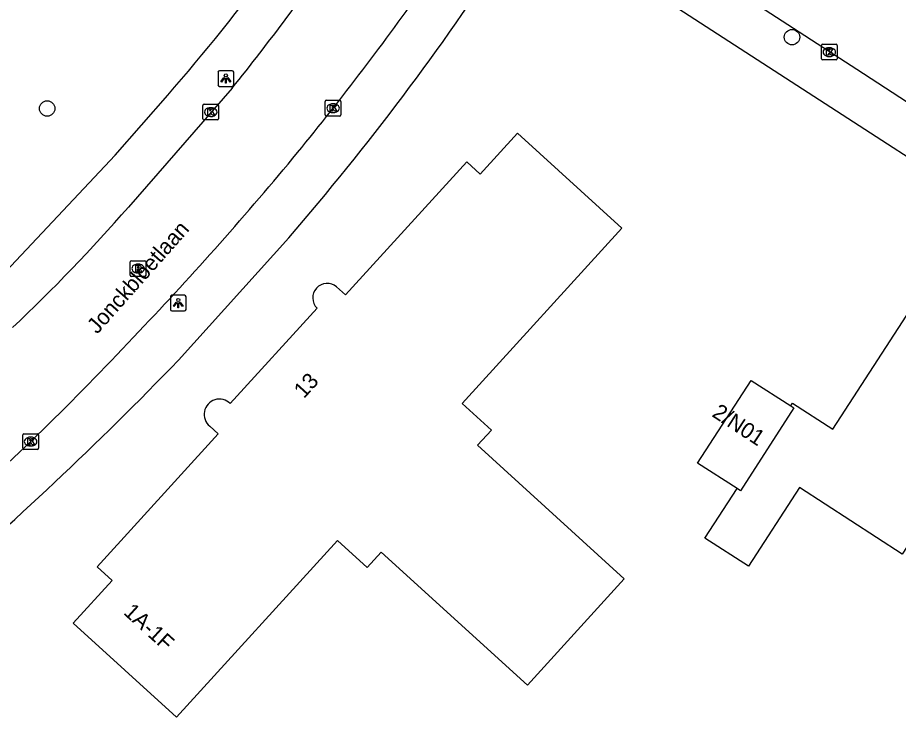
# Model space of a CAD drawing. Extents: x 161141 to 161601, y 381708 to 382245.
# Drawn here: x 161326.4 to 161382.4, y 382081.9 to 382126.6 of the extents above; entities that cross this region are included whole.
import ezdxf

# ---------------------------------------------------------------- set-up
doc = ezdxf.new("R2010")
doc.units = 0
for name, color, linetype in [('IMGEO_Boom', 7, 'Continuous'), ('IMGEO_Kolk', 7, 'Continuous'), ('IMGEO_Lichtpunt', 7, 'Continuous'), ('IMGEO_Openbare_ruimte_label', 7, 'Continuous'), ('IMGEO_Pand', 7, 'Continuous'), ('IMGEO_Pand_nummerreeks', 7, 'Continuous'), ('IMGEO_Rijbaan_lokaal_open', 7, 'Continuous'), ('IMGEO_Rioolput', 7, 'Continuous'), ('IMGEO_Voetpad_open', 7, 'Continuous')]:
    doc.layers.add(name, color=color, linetype=linetype)

msp = doc.modelspace()

# ---------------------------------------------------------------- linework, layer by layer
at = {"layer": 'IMGEO_Boom'}
for centre in [(161375.634, 382125.332), (161328.284, 382120.794)]:
    msp.add_circle(centre, 0.489, dxfattribs=at)
at = {"layer": 'IMGEO_Kolk'}
for p, q in [((161377.504, 382123.953), (161377.504, 382124.805)), ((161377.579, 382124.879), (161378.431, 382124.879)), ((161377.992, 382124.659), (161378.017, 382124.659)), ((161378.505, 382124.805), (161378.505, 382123.953)), ((161378.431, 382123.879), (161377.579, 382123.879)), ((161378.015, 382124.099), (161377.99, 382124.099)), ((161338.258, 382121.065), (161339.11, 382121.065)), ((161345.96, 382120.389), (161345.96, 382121.241)), ((161346.035, 382121.315), (161346.887, 382121.315)), ((161346.448, 382121.095), (161346.473, 382121.095)), ((161346.961, 382121.241), (161346.961, 382120.389)), ((161338.183, 382120.139), (161338.183, 382120.991)), ((161338.671, 382120.845), (161338.696, 382120.845)), ((161339.184, 382120.991), (161339.184, 382120.139)), ((161346.471, 382120.535), (161346.446, 382120.535)), ((161339.11, 382120.065), (161338.258, 382120.065)), ((161338.694, 382120.285), (161338.669, 382120.285)), ((161346.887, 382120.315), (161346.035, 382120.315)), ((161326.728, 382099.183), (161326.728, 382100.035)), ((161326.803, 382100.109), (161327.655, 382100.109)), ((161327.216, 382099.889), (161327.241, 382099.889)), ((161327.729, 382100.035), (161327.729, 382099.183)), ((161327.239, 382099.329), (161327.214, 382099.329)), ((161327.655, 382099.109), (161326.803, 382099.109))]:
    msp.add_line(p, q, dxfattribs=at)
for points in [[(161377.504, 382123.953), (161377.504, 382124.805)], [(161377.579, 382124.879), (161378.431, 382124.879)], [(161377.825, 382124.579), (161377.948, 382124.579), (161377.948, 382124.428), (161378.078, 382124.579), (161378.242, 382124.579), (161378.096, 382124.428), (161378.249, 382124.179), (161378.097, 382124.179), (161378.012, 382124.343), (161377.948, 382124.276), (161377.948, 382124.179), (161377.825, 382124.179), (161377.825, 382124.579)], [(161378.505, 382124.805), (161378.505, 382123.953)], [(161378.431, 382123.879), (161377.579, 382123.879)], [(161338.258, 382121.065), (161339.11, 382121.065)], [(161345.96, 382120.389), (161345.96, 382121.241)], [(161346.035, 382121.315), (161346.887, 382121.315)], [(161346.281, 382121.015), (161346.404, 382121.015), (161346.404, 382120.864), (161346.534, 382121.015), (161346.698, 382121.015), (161346.552, 382120.864), (161346.705, 382120.615), (161346.553, 382120.615), (161346.468, 382120.779), (161346.404, 382120.712), (161346.404, 382120.615), (161346.281, 382120.615), (161346.281, 382121.015)], [(161346.961, 382121.241), (161346.961, 382120.389)], [(161338.183, 382120.139), (161338.183, 382120.991)], [(161338.504, 382120.765), (161338.627, 382120.765), (161338.627, 382120.614), (161338.757, 382120.765), (161338.921, 382120.765), (161338.775, 382120.614), (161338.928, 382120.365), (161338.776, 382120.365), (161338.691, 382120.529), (161338.627, 382120.462), (161338.627, 382120.365), (161338.504, 382120.365), (161338.504, 382120.765)], [(161339.184, 382120.991), (161339.184, 382120.139)], [(161339.11, 382120.065), (161338.258, 382120.065)], [(161346.887, 382120.315), (161346.035, 382120.315)], [(161326.728, 382099.183), (161326.728, 382100.035)], [(161326.803, 382100.109), (161327.655, 382100.109)], [(161327.049, 382099.809), (161327.172, 382099.809), (161327.172, 382099.658), (161327.302, 382099.809), (161327.466, 382099.809), (161327.32, 382099.658), (161327.473, 382099.409), (161327.321, 382099.409), (161327.236, 382099.573), (161327.172, 382099.506), (161327.172, 382099.409), (161327.049, 382099.409), (161327.049, 382099.809)], [(161327.729, 382100.035), (161327.729, 382099.183)], [(161327.655, 382099.109), (161326.803, 382099.109)]]:
    msp.add_lwpolyline(points, dxfattribs=at)
for centre, start, end in [((161377.581, 382124.803), 91.552, 178.448), ((161377.581, 382124.803), 91.552, 178.448), ((161378.429, 382124.803), 1.552, 88.448), ((161378.429, 382124.803), 1.552, 88.448), ((161377.581, 382123.955), 181.552, 268.448), ((161377.581, 382123.955), 181.552, 268.448), ((161378.429, 382123.955), 271.552, 358.448), ((161378.429, 382123.955), 271.552, 358.448), ((161338.26, 382120.989), 91.552, 178.448), ((161338.26, 382120.989), 91.552, 178.448), ((161339.108, 382120.989), 1.552, 88.448), ((161339.108, 382120.989), 1.552, 88.448), ((161346.037, 382121.239), 91.552, 178.448), ((161346.037, 382121.239), 91.552, 178.448), ((161346.885, 382121.239), 1.552, 88.448), ((161346.885, 382121.239), 1.552, 88.448), ((161338.26, 382120.141), 181.552, 268.448), ((161338.26, 382120.141), 181.552, 268.448), ((161339.108, 382120.141), 271.552, 358.448), ((161339.108, 382120.141), 271.552, 358.448), ((161346.037, 382120.391), 181.552, 268.448), ((161346.037, 382120.391), 181.552, 268.448), ((161346.885, 382120.391), 271.552, 358.448), ((161346.885, 382120.391), 271.552, 358.448), ((161326.805, 382100.033), 91.552, 178.448), ((161326.805, 382100.033), 91.552, 178.448), ((161327.653, 382100.033), 1.552, 88.448), ((161327.653, 382100.033), 1.552, 88.448), ((161326.805, 382099.185), 181.552, 268.448), ((161326.805, 382099.185), 181.552, 268.448), ((161327.653, 382099.185), 271.552, 358.448), ((161327.653, 382099.185), 271.552, 358.448)]:
    msp.add_arc(centre, 0.0765, start, end, dxfattribs=at)
for centre, major_axis, ratio, start_param, end_param in [((161377.991, 382124.379), (-0.387, 0.002), 0.722429, 4.712389, 7.853982), ((161378.016, 382124.379), (-0.39, 0.002), 0.717154, 1.570796, 4.712389), ((161346.447, 382120.815), (-0.387, 0.002), 0.722429, 4.712389, 7.853982), ((161346.472, 382120.815), (-0.39, 0.002), 0.717154, 1.570796, 4.712389), ((161338.67, 382120.565), (-0.387, 0.002), 0.722429, 4.712389, 7.853982), ((161338.695, 382120.565), (-0.39, 0.002), 0.717154, 1.570796, 4.712389), ((161327.215, 382099.609), (-0.387, 0.002), 0.722429, 4.712389, 7.853982), ((161327.24, 382099.609), (-0.39, 0.002), 0.717154, 1.570796, 4.712389)]:
    msp.add_ellipse(centre, major_axis=major_axis, ratio=ratio, start_param=start_param, end_param=end_param, dxfattribs=at)
at = {"layer": 'IMGEO_Lichtpunt'}
for p, q in [((161339.143, 382123.103), (161339.143, 382122.296)), ((161339.143, 382123.103), (161339.143, 382122.296)), ((161340.045, 382123.198), (161339.237, 382123.198)), ((161340.045, 382123.198), (161339.237, 382123.198)), ((161340.139, 382122.296), (161340.139, 382123.103)), ((161340.139, 382122.296), (161340.139, 382123.103)), ((161339.237, 382122.202), (161340.045, 382122.202)), ((161339.237, 382122.202), (161340.045, 382122.202)), ((161336.116, 382108.817), (161336.116, 382108.01)), ((161336.116, 382108.817), (161336.116, 382108.01)), ((161337.018, 382108.912), (161336.21, 382108.912)), ((161337.018, 382108.912), (161336.21, 382108.912)), ((161337.112, 382108.01), (161337.112, 382108.817)), ((161337.112, 382108.01), (161337.112, 382108.817)), ((161336.21, 382107.916), (161337.018, 382107.916)), ((161336.21, 382107.916), (161337.018, 382107.916))]:
    msp.add_line(p, q, dxfattribs=at)
for points in [[(161339.517, 382122.767), (161339.556, 382122.739), (161339.368, 382122.477), (161339.33, 382122.504), (161339.517, 382122.767)], [(161339.619, 382122.719), (161339.666, 382122.719), (161339.666, 382122.397), (161339.619, 382122.397), (161339.619, 382122.719)], [(161339.729, 382122.739), (161339.767, 382122.766), (161339.954, 382122.504), (161339.915, 382122.476), (161339.729, 382122.739)], [(161336.49, 382108.481), (161336.529, 382108.453), (161336.341, 382108.191), (161336.303, 382108.218), (161336.49, 382108.481)], [(161336.592, 382108.433), (161336.639, 382108.433), (161336.639, 382108.111), (161336.592, 382108.111), (161336.592, 382108.433)], [(161336.702, 382108.453), (161336.74, 382108.48), (161336.927, 382108.218), (161336.888, 382108.19), (161336.702, 382108.453)]]:
    msp.add_lwpolyline(points, dxfattribs=at)
for centre in [(161339.642, 382122.901), (161336.615, 382108.615)]:
    msp.add_circle(centre, 0.0994, dxfattribs=at)
for centre, start, end in [((161339.237, 382123.103), 90, 180), ((161339.237, 382123.103), 90, 180), ((161340.045, 382123.103), 0, 90), ((161340.045, 382123.103), 0, 90), ((161339.237, 382122.296), 180, 270), ((161339.237, 382122.296), 180, 270), ((161340.045, 382122.296), 270, 0), ((161340.045, 382122.296), 270, 360), ((161336.21, 382108.817), 90, 180), ((161336.21, 382108.817), 90, 180), ((161337.018, 382108.817), 0, 90), ((161337.018, 382108.817), 0, 90), ((161336.21, 382108.01), 180, 270), ((161336.21, 382108.01), 180, 270), ((161337.018, 382108.01), 270, 0), ((161337.018, 382108.01), 270, 360)]:
    msp.add_arc(centre, 0.0946, start, end, dxfattribs=at)
at = {"layer": 'IMGEO_Pand'}
for points in [[(161346.685, 382109.457), (161347.252, 382108.941), (161354.956, 382117.404), (161355.81, 382116.625), (161358.18, 382119.228), (161364.817, 382113.186), (161354.661, 382102.03), (161356.521, 382100.336), (161355.647, 382099.376), (161364.97, 382090.887), (161358.81, 382084.121)], [(161375.556, 382101.873), (161375.671, 382102.05), (161378.237, 382100.391), (161384.729, 382110.433), (161388.052, 382108.285), (161388.906, 382108.722), (161390.752, 382107.529), (161390.705, 382106.586), (161391.463, 382106.096), (161388.749, 382101.898), (161385.152, 382096.335), (161382.643, 382092.455), (161376.11, 382096.68), (161372.874, 382091.675), (161370.095, 382093.472), (161372.141, 382096.619)], [(161339.916, 382102.024), (161345.438, 382108.089)], [(161372.141, 382096.619), (161369.633, 382098.24), (161373.035, 382103.503), (161375.556, 382101.873)], [(161375.556, 382101.873), (161375.755, 382101.744), (161372.353, 382096.482), (161372.141, 382096.619)], [(161358.81, 382084.121), (161349.515, 382092.582), (161348.62, 382091.598), (161346.729, 382093.319), (161336.5, 382082.084), (161329.934, 382088.061), (161332.405, 382090.775), (161331.456, 382091.639), (161339.157, 382100.098), (161338.619, 382100.588)]]:
    msp.add_lwpolyline(points, dxfattribs=at)
for centre, radius, start, end in [((161346.091, 382108.746), 0.926, 50.1574, 225.1411), ((161339.23, 382101.34), 0.969, 44.9305, 230.8926)]:
    msp.add_arc(centre, radius, start, end, dxfattribs=at)
at = {"layer": 'IMGEO_Rijbaan_lokaal_open'}
for points in [[(161499.796, 382045.589), (161498.051, 382046.741), (161477.592, 382059.945), (161473.195, 382062.836), (161460.477, 382071.037), (161453.542, 382075.54), (161442.527, 382082.644), (161435.549, 382087.163), (161421.669, 382096.147), (161415.306, 382100.289), (161401.761, 382109.008), (161398.574, 382111.058), (161389.569, 382116.981), (161386.277, 382119.018), (161382.915, 382121.211), (161379.746, 382123.279), (161360.833, 382135.554)], [(161340.039, 382122.079), (161333.454, 382114.524)]]:
    msp.add_lwpolyline(points, dxfattribs=at)
for centre, radius, start, end in [((161203.791, 382231.164), 174.537, 321.31806, 325.051), ((161196.442, 382238.738), 190.818, 320.74581, 324.77255), ((161186.941, 382247.202), 203.531, 316.31175, 320.59327), ((161247.867, 382189.45), 113.75, 313.43897, 318.80017), ((161201.158, 382230.421), 181.674, 311.8463, 317.04167)]:
    msp.add_arc(centre, radius, start, end, dxfattribs=at)
at = {"layer": 'IMGEO_Rioolput'}
for p, q in [((161333.564, 382110.188), (161333.564, 382111.04)), ((161333.639, 382111.114), (161334.491, 382111.114)), ((161334.565, 382111.04), (161334.565, 382110.188)), ((161334.052, 382110.894), (161334.077, 382110.894)), ((161334.491, 382110.114), (161333.639, 382110.114)), ((161334.075, 382110.334), (161334.05, 382110.334))]:
    msp.add_line(p, q, dxfattribs=at)
for points in [[(161333.564, 382110.188), (161333.564, 382111.04)], [(161333.639, 382111.114), (161334.491, 382111.114)], [(161334.565, 382111.04), (161334.565, 382110.188)], [(161334.153, 382110.812), (161333.901, 382110.814), (161333.901, 382110.414)], [(161333.901, 382110.414), (161334.025, 382110.414), (161334.025, 382110.576), (161334.036, 382110.576)], [(161334.079, 382110.733), (161334.025, 382110.733), (161334.025, 382110.652)], [(161334.025, 382110.652), (161334.077, 382110.652)], [(161334.083, 382110.547), (161334.154, 382110.414), (161334.294, 382110.414), (161334.229, 382110.54)], [(161334.491, 382110.114), (161333.639, 382110.114)]]:
    msp.add_lwpolyline(points, dxfattribs=at)
for centre, radius, start, end in [((161333.641, 382111.038), 0.0765, 91.552, 178.448), ((161333.641, 382111.038), 0.0765, 91.552, 178.448), ((161334.489, 382111.038), 0.0765, 1.552, 88.448), ((161334.489, 382111.038), 0.0765, 1.552, 88.448), ((161334.035, 382110.523), 0.0533, 26.0293, 88.6989), ((161334.061, 382110.841), 0.19, 274.7715, 282.9687), ((161334.085, 382110.637), 0.0964, 77.0061, 93.1865), ((161334.099, 382110.694), 0.0378, 276.6634, 79.6772), ((161334.152, 382110.702), 0.109, 350.3612, 89.416), ((161334.15, 382110.702), 0.112, 277.5842, 350.9817), ((161334.134, 382110.487), 0.108, 29.5134, 73.7905), ((161333.641, 382110.19), 0.0765, 181.552, 268.448), ((161333.641, 382110.19), 0.0765, 181.552, 268.448), ((161334.489, 382110.19), 0.0765, 271.552, 358.448), ((161334.489, 382110.19), 0.0765, 271.552, 358.448)]:
    msp.add_arc(centre, radius, start, end, dxfattribs=at)
for centre, major_axis, ratio, start_param, end_param in [((161334.051, 382110.614), (-0.387, 0.002), 0.722429, 4.712389, 7.853982), ((161334.076, 382110.614), (-0.39, 0.002), 0.717154, 1.570796, 4.712389)]:
    msp.add_ellipse(centre, major_axis=major_axis, ratio=ratio, start_param=start_param, end_param=end_param, dxfattribs=at)
at = {"layer": 'IMGEO_Voetpad_open'}
for points in [[(161359.011, 382133.266), (161498.24, 382043.117)], [(161324.958, 382109.709), (161332.601, 382117.82), (161335.947, 382121.635)], [(161343.639, 382112.574), (161336.623, 382104.782)]]:
    msp.add_lwpolyline(points, dxfattribs=at)
for centre, radius, start, end in [((161232.712, 382211.238), 136.697, 319.04376, 328.08342), ((161216.665, 382222.387), 167.873, 319.14523, 327.03259), ((161172.719, 382262.803), 227.673, 310.48144, 316.04693)]:
    msp.add_arc(centre, radius, start, end, dxfattribs=at)

# ---------------------------------------------------------------- texts
at = {"layer": 'IMGEO_Openbare_ruimte_label'}
msp.add_text('Jonckbloetlaan', height=1, rotation=48.4854, dxfattribs=at).set_placement((161331.465, 382106.401))
at = {"layer": 'IMGEO_Pand_nummerreeks'}
for s, rotation, p in [('13', 47.6831, (161344.607, 382102.305)), ('2/N01', 326.671, (161370.489, 382101.247)), ('1A-1F', 317.7591, (161333.082, 382088.674))]:
    msp.add_text(s, height=1, rotation=rotation, dxfattribs=at).set_placement(p)

doc.saveas('drawing.dxf')
